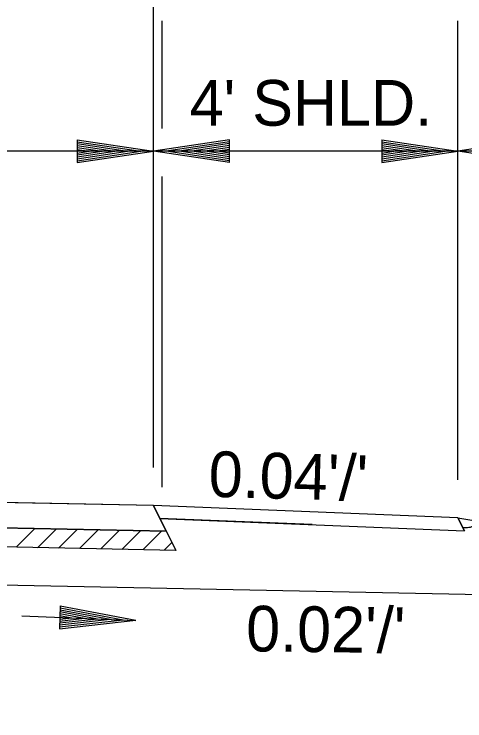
# Model space of a CAD drawing. Extents: x -900 to 15312, y 1857 to 2945.
# Drawn here: x 2232.9 to 2292.1, y 2116.4 to 2209.2 of the extents above; entities that cross this region are included whole.
import ezdxf

# ---------------------------------------------------------------- set-up
doc = ezdxf.new("R2010")
doc.units = 0
for name, color, linetype in [('Default', 7, 'Continuous'), ('R_Annotation', 7, 'Continuous'), ('R_Dimension', 7, 'Continuous')]:
    doc.layers.add(name, color=color, linetype=linetype)

msp = doc.modelspace()

# ---------------------------------------------------------------- linework, layer by layer
at = {"layer": 'Default'}
for p, q in [((2251.179, 2144.678), (2231.179, 2145.078)), ((2252.031, 2142.976), (2251.179, 2144.678)), ((2252.863, 2141.31), (2252.031, 2142.976)), ((2231.179, 2141.744), (2252.863, 2141.31)), ((2233.168, 2139.204), (2235.619, 2141.655)), ((2235.941, 2139.148), (2238.392, 2141.6)), ((2238.714, 2139.093), (2241.165, 2141.544)), ((2241.487, 2139.038), (2243.938, 2141.489)), ((2244.26, 2138.982), (2246.711, 2141.434)), ((2247.033, 2138.927), (2249.484, 2141.378)), ((2249.806, 2138.871), (2252.257, 2141.323)), ((2252.579, 2138.816), (2253.6, 2139.837))]:
    msp.add_line(p, q, dxfattribs=at)
at = {"layer": 'R_Annotation'}
for p, q in [((2251.179, 2144.678), (2141.179, 2146.878)), ((2251.179, 2144.678), (2254.126, 2138.785)), ((2291.179, 2143.078), (2251.179, 2144.678)), ((2272.031, 2142.176), (2252.031, 2142.976)), ((2291.179, 2143.078), (2292.031, 2141.376)), ((2291.179, 2143.078), (2451.179, 2116.412)), ((2252.863, 2141.31), (2231.179, 2141.744)), ((2254.126, 2138.785), (2231.179, 2139.244)), ((2359.603, 2131.674), (2231.179, 2134.243))]:
    msp.add_line(p, q, dxfattribs=at)
msp.add_open_spline([(2294.226, 2142.57), (2294.2, 2142.534), (2294.077, 2142.383), (2293.954, 2142.288), (2293.638, 2142.109), (2293.44, 2142.013), (2292.936, 2141.854), (2292.652, 2141.782), (2292.215, 2141.755), (2292.07, 2141.754), (2291.925, 2141.763)], degree=3, dxfattribs=at)
at = {"layer": 'R_Dimension'}
for p, q in [((2251.179, 2191.212), (2251.179, 2257.454)), ((2252.308, 2194.203), (2252.308, 2208.333)), ((2291.179, 2148.082), (2291.179, 2208.333)), ((2241.179, 2192.712), (2251.179, 2191.212)), ((2241.179, 2192.712), (2241.179, 2189.712)), ((2241.179, 2192.462), (2249.509, 2191.212)), ((2241.179, 2192.207), (2247.789, 2191.212)), ((2241.179, 2191.957), (2246.124, 2191.212)), ((2261.179, 2192.712), (2251.179, 2191.212)), ((2261.179, 2192.462), (2252.849, 2191.212)), ((2261.179, 2192.207), (2254.569, 2191.212)), ((2261.179, 2191.957), (2256.234, 2191.212)), ((2261.179, 2189.712), (2261.179, 2192.712)), ((2281.179, 2192.712), (2291.179, 2191.212)), ((2281.179, 2192.712), (2281.179, 2189.712)), ((2281.179, 2192.462), (2289.509, 2191.212)), ((2281.179, 2192.207), (2287.789, 2191.212)), ((2281.179, 2191.957), (2286.124, 2191.212)), ((2301.179, 2192.712), (2291.179, 2191.212)), ((2359.603, 2191.212), (1922.751, 2191.212)), ((2241.179, 2191.697), (2244.429, 2191.212)), ((2241.179, 2191.447), (2242.759, 2191.212)), ((2241.179, 2189.712), (2251.179, 2191.212)), ((2241.179, 2190.722), (2244.429, 2191.212)), ((2241.179, 2190.217), (2247.789, 2191.212)), ((2241.179, 2189.962), (2249.509, 2191.212)), ((2241.179, 2190.467), (2246.124, 2191.212)), ((2241.179, 2190.977), (2242.759, 2191.212)), ((2251.179, 2149.682), (2251.179, 2191.212)), ((2261.179, 2189.712), (2251.179, 2191.212)), ((2261.179, 2189.962), (2252.849, 2191.212)), ((2261.179, 2190.217), (2254.569, 2191.212)), ((2261.179, 2190.467), (2256.234, 2191.212)), ((2261.179, 2191.702), (2257.929, 2191.212)), ((2261.179, 2190.727), (2257.929, 2191.212)), ((2261.179, 2191.447), (2259.599, 2191.212)), ((2261.179, 2190.977), (2259.599, 2191.212)), ((2281.179, 2191.697), (2284.429, 2191.212)), ((2281.179, 2191.447), (2282.759, 2191.212)), ((2281.179, 2189.712), (2291.179, 2191.212)), ((2281.179, 2190.722), (2284.429, 2191.212)), ((2281.179, 2190.217), (2287.789, 2191.212)), ((2281.179, 2189.962), (2289.509, 2191.212)), ((2281.179, 2190.467), (2286.124, 2191.212)), ((2281.179, 2190.977), (2282.759, 2191.212)), ((2301.179, 2189.712), (2291.179, 2191.212)), ((2252.308, 2147.089), (2252.308, 2187.878)), ((2251.179, 2144.678), (2252.031, 2142.976)), ((2291.179, 2143.078), (2251.179, 2144.678)), ((2252.031, 2142.976), (2292.031, 2141.376)), ((2292.031, 2141.376), (2291.179, 2143.078)), ((2238.941, 2131.511), (2238.821, 2128.514)), ((2238.911, 2130.757), (2243.822, 2129.815)), ((2238.921, 2131.007), (2245.486, 2129.748)), ((2238.931, 2131.261), (2247.205, 2129.68)), ((2238.941, 2131.511), (2248.873, 2129.613)), ((2233.887, 2130.212), (2248.875, 2129.612)), ((2238.851, 2129.268), (2243.822, 2129.815)), ((2238.862, 2129.523), (2242.129, 2129.883)), ((2238.872, 2129.778), (2240.46, 2129.949)), ((2238.891, 2130.247), (2240.46, 2129.949)), ((2238.901, 2130.497), (2242.129, 2129.883)), ((2238.821, 2128.514), (2248.873, 2129.613)), ((2238.831, 2128.763), (2247.205, 2129.68)), ((2238.841, 2129.018), (2245.486, 2129.748))]:
    msp.add_line(p, q, dxfattribs=at)

# ---------------------------------------------------------------- texts
at = {"layer": 'R_Annotation'}
msp.add_text("4' SHLD.", height=6, dxfattribs=at).set_placement((2255.94, 2194.563))
for s, rotation, p in [("0.04'/'", 358.39778, (2258.371, 2145.847)), ("0.02'/'", 359.35054, (2263.336, 2125.543))]:
    msp.add_text(s, height=6, rotation=rotation, dxfattribs=at).set_placement(p)

doc.saveas('drawing.dxf')
